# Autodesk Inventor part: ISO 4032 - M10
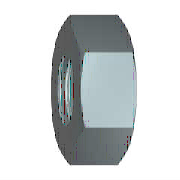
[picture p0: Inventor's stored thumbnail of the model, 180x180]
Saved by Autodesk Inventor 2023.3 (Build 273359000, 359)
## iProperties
Created: 2022-02
Part Number: ISO 4032 - M10
Material: Acier inoxydable 440C
Description: Ecrous hexagonaux, style 1 - Produit de classes A et B
Document SubType Name: Modeling
Standard: ISO 4032
Designer: Thier
Standard Revision: Fourth edition 2012-12-15
Standards Organization: ISO
Language: fr-FR
Size Designation: M10
Categories: <MemberInstance><Categories><Category DisplayName="Visserie" InternalName="e4da775c-781d-43d5-af7c-5136215cf5a6" Mnemonic="FSTN"><Category DisplayName="Ecrous"
Density: 7.75 g/cm^3
Appearance: Semi-poli
IsCustomPart: 0
Author: Thier
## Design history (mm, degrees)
sketch "Esquisse1"
  geometry: L1 (-9.238, 0)-(-4.619, 8); L2 (-4.619, 8)-(4.619, 8); L3 (4.619, 8)-(9.238, 0); L4 (9.238, 0)-(4.619, -8); L5 (4.619, -8)-(-4.619, -8); L6 (-4.619, -8)-(-9.238, 0); 2 further points
  constraints: 12 end point, 1 coincident, 1 horizontal, 11 other
  dimensions: "d0" = 18.47521 distance of L3.end L1.start (= 1.1547 x SW)
extrude "Corps" new body sketch "Esquisse1" distance "d1" = 8.4 (= KOH); taper "d2" = 0 deg
sketch "Esquisse2"
  geometry: L1 (0, 4.619)-(0, 9.238) reference; L2 (0, 9.238)-(8.4, 9.238) reference; L3 (8.4, 4.619)-(8.4, 9.238) reference; L4 (-1.68, 0)-(10.08, 0) reference; L5 (1.119, 9.238)-(0, 7.3); L6 (7.281, 9.238)-(8.4, 7.3)
  constraints: 4 end point, 4 point on line
  dimensions: "d3" = 30 deg angle of L1 L5 (= ANG1); "d4" = 30 deg angle of L3 L6 (= ANG2); "d5" = 14.6 diameter of L5.end L4 (= SW0); "d6" = 14.6 diameter of L6.end L4 (= SW01)
revolve "Chanfrein1" sketch "Esquisse2" stored, may be unused: angle "d7" = 90 deg
sketch "Esquisse3"
  geometry: 4 further points
  constraints: 1 coincident, 1 other
hole "Filetage" sketch "Esquisse3" at (0, 0) diameter "d25" = 8.376; stored, may be unused: countersink angle "d29" = 82 deg, drill point angle "d31" = 118 deg; dims "d26" = 6, "d27" = 4, "d28" = 2, "d30" = 8
workaxis "Work Axis1"
workplane "Work Plane1"
body "Solid1"
chamfer "Chanfrein2" distance "d8" = 0.8119 (= -0.5 x GD1 + 0.5 x NND); stored, may be unused: angle "d9" = 30 deg, second distance "d40" = 0.8119 (= -0.5 x GD1 + 0.5 x NND)
chamfer "Chanfrein3" distance "d10" = 0.8119 (= -0.5 x GD1 + 0.5 x NND); stored, may be unused: angle "d11" = 30 deg, second distance "d41" = 0.8119 (= -0.5 x GD1 + 0.5 x NND)
other parameters: "ANG1" = 30 deg [user parameter; used in 1 equation term], "ANG2" = 30 deg [user parameter; used in 1 equation term], "KOH" = 8.4 [user parameter; used in 1 equation term], "SW" = 16 [user parameter; used in 2 equation terms], "SW0" = 14.6 [user parameter; used in 2 equation terms], "SW01" = 14.6 (= SW0) [user parameter; used in 1 equation term], "GD1" = 8.3762 (computed from THREADDIA, PTC, TOA) [user parameter; used in 4 equation terms], "d13" = 0, "d14" = 0, "d39" = 0, "d42" = 0, "GUL" = 0.8119 (= 0.541266 x PTC) [user parameter], "TPU" = 6.66667 (computed from PTC) [user parameter], "TOA" = 30 deg [user parameter; used in 1 equation term], "PTC" = 1.5 [user parameter; used in 4 equation terms], "E0" = 18.48 (= 1.155 x SW) [user parameter], "GAL" = 0.8119 (= 0.541266 x PTC) [user parameter]
